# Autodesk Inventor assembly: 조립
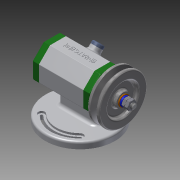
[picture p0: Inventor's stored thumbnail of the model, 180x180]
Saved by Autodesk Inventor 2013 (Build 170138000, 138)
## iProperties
Created: 2017-04
Part Number: 조립
Document SubType Name: Assembly
Designer: Administrator
Mass: 1391.94 g
Surface Area: 1146.73 cm^2
Volume: 352.369 cm^3
Density: 3.95023 g/cm^3
Author: Administrator
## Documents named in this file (14)
- C:\Users\Administrator\Desktop\470608V1005\조립.iam
- C:\Users\Administrator\Desktop\470608V1005\본체.ipt
- C:\Users\Administrator\Desktop\470608V1005\V벨트풀리.ipt
- C:\Users\Administrator\Desktop\470608V1005\고무캡.ipt
- C:\Users\Administrator\Desktop\470608V1005\너트 M 8.ipt
- C:\Users\Administrator\Desktop\470608V1005\뒤커버.ipt
- C:\Users\Administrator\Desktop\470608V1005\베어링 15 x 32 x 9.ipt
- C:\Users\Administrator\Desktop\470608V1005\볼트 M4 x 12.ipt
- C:\Users\Administrator\Desktop\470608V1005\스프링와셔 8.ipt
- C:\Users\Administrator\Desktop\470608V1005\앞커버.ipt
- C:\Users\Administrator\Desktop\470608V1005\오일 실 15 25 7.ipt
- C:\Users\Administrator\Desktop\470608V1005\와셔 8x17.ipt
- C:\Users\Administrator\Desktop\470608V1005\축.ipt
- C:\Users\Administrator\Desktop\470608V1005\키 3 x 3 x 12.ipt
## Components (2 placed, 2 different names)
1. V벨트풀리:1
2. 고무캡:1
